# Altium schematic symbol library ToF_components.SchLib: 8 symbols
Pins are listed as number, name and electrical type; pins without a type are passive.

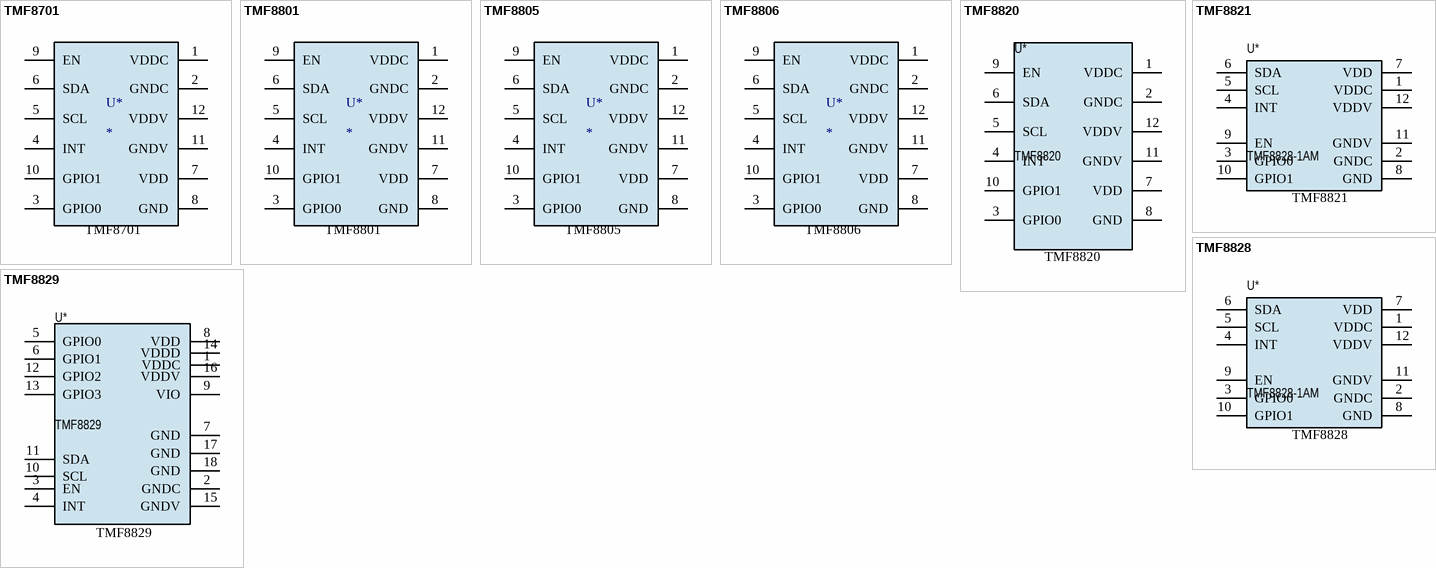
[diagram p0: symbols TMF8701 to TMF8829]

## TMF8701
designator U*
footprint TMF8701
pins: 1 VDDC, 2 GNDC, 3 GPIO0, 4 INT (power), 5 SCL, 6 SDA, 7 VDD, 8 GND, 9 EN, 10 GPIO1, 11 GNDV, 12 VDDV

## TMF8801
designator U*
footprint TMF8801
pins: 1 VDDC, 2 GNDC, 3 GPIO0, 4 INT (power), 5 SCL, 6 SDA, 7 VDD, 8 GND, 9 EN, 10 GPIO1, 11 GNDV, 12 VDDV

## TMF8805
designator U*
footprint TMF8805
pins: 1 VDDC, 2 GNDC, 3 GPIO0, 4 INT (power), 5 SCL, 6 SDA, 7 VDD, 8 GND, 9 EN, 10 GPIO1, 11 GNDV, 12 VDDV

## TMF8806
designator U*
footprint TMF8806
pins: 1 VDDC, 2 GNDC, 3 GPIO0, 4 INT (power), 5 SCL, 6 SDA, 7 VDD, 8 GND, 9 EN, 10 GPIO1, 11 GNDV, 12 VDDV

## TMF8820
designator U*
Manufacturer 1: ams-OSRAM USA INC.; Manufacturer Part Number 1: TMF8829
footprint TMF8820
pins: 1 VDDC (power), 2 GNDC (power), 3 GPIO0, 4 INT (power), 5 SCL (power), 6 SDA (power), 7 VDD (power), 8 GND, 9 EN (power), 10 GPIO1, 11 GNDV, 12 VDDV (power)

## TMF8821
designator U*, comment TMF8828-1AM
Manufacturer 1: ams-OSRAM USA INC.
footprint TMF8821
pins: 1 VDDC (power), 2 GNDC, 3 GPIO0 (power), 4 INT, 5 SCL, 6 SDA (power), 7 VDD (power), 8 GND, 9 EN, 10 GPIO1 (power), 11 GNDV, 12 VDDV

## TMF8828
designator U*, comment TMF8828-1AM
Manufacturer 1: ams-OSRAM USA INC.
footprint TMF8828 (Optical Sensor 0.394" ~ 196.85" (10mm ~ 5000mm) Push-Pull Output)
pins: 1 VDDC (power), 2 GNDC, 3 GPIO0 (power), 4 INT, 5 SCL, 6 SDA (power), 7 VDD (power), 8 GND, 9 EN, 10 GPIO1 (power), 11 GNDV, 12 VDDV

## TMF8829
designator U*
Manufacturer 1: ams-OSRAM USA INC.
footprint TMF8829
pins: 1 VDDC (power), 2 GNDC, 3 EN (power), 4 INT (power), 5 GPIO0, 6 GPIO1, 7 GND, 8 VDD (power), 9 VIO (power), 10 SCL (power), 11 SDA (power), 12 GPIO2 (power), 13 GPIO3, 14 VDDD, 15 GNDV, 16 VDDV, 17 GND, 18 GND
